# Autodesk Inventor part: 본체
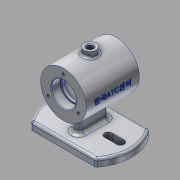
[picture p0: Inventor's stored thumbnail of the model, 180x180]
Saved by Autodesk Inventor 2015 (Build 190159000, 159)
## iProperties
Created: 2017-12
Part Number: 본체
Material: 알루미늄 6061
Document SubType Name: Modeling
Designer: SCD-A03
Density: 2.7 g/cm^3
Appearance: 알루미늄 - 평지
Author: SCD-A03
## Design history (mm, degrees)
sketch "스케치1"
  geometry: C1 r 30 at (0, 0); 1 further point
  constraints: 1 centre point, 1 coincident
  dimensions: "d0" = 60 diameter of C1
extrude "돌출1" new body sketch "스케치1" stored distance "d1" = 70; taper "d2" = 0 deg
node "작업 평면1"
sketch "스케치2"
  geometry: L1 (-42.426, 35)-(42.426, 35); L2 (42.426, -35)-(-42.426, -35); A1 r 55 centre (0, 0) between (-42.426, 35) and (-42.426, -35); A2 r 55 centre (0, 0) between (42.426, -35) and (42.426, 35); 2 further points
  constraints: 4 end point, 4 point on circle, 2 centre point, 1 coincident, 1 horizontal, 1 horizontal alignment, 1 parallel
  dimensions: "d5" = 70 distance between parallel lines of L2 L1; "d6" = 35 distance from line of point (0, 0) L1
extrude "돌출2" join sketch "스케치2" distance "d7" = 10; taper "d8" = 0 deg
sketch "스케치3"
  geometry: L1 (-5, 15.086)-(5, 15.086); L2 (5, 15.086)-(5, -14.914); L3 (5, -14.914)-(-5, -14.914); L4 (-5, -14.914)-(-5, 15.086); A1 r 55 centre (0, 0) between (-42.426, 35) and (-42.426, -35) reference; 3 further points
  constraints: 8 end point, 3 horizontal alignment, 2 midpoint, 2 parallel, 1 horizontal, 1 perpendicular, 4 other
  dimensions: "d18" = 5 distance from line of A1.centre L4; "d19" = 10 distance between parallel lines of L2 L4; "d20" = 30 distance of L1.end L2.end
extrude "돌출3" join sketch "스케치3" stored distance "d12" = 10; taper "d13" = 0 deg
sketch "스케치5"
  geometry: L1 (40, 5)-(24, 5); L2 (24, 5)-(24, -5); L3 (24, -5)-(40, -5); L4 (40, -5)-(40, 5); L5 (0, 0)-(0, -14.914); L6 (-24, 5)-(-24, -5); L7 (-40, 5)-(-24, 5); L8 (-24, -5)-(-40, -5); L9 (-40, -5)-(-40, 5); A1 r 5 centre (0, -14.914) between (-5, -14.914) and (5, -14.914) reference; A2 r 55 centre (0, 0) between (-42.426, 35) and (-42.426, -35) reference; A3 r 55 centre (0, 0) between (42.426, -35) and (42.426, 35) reference; 6 further points
  constraints: 18 end point, 7 symmetric about line, 4 vertical alignment, 3 vertical, 2 coincident, 2 midpoint, 2 parallel, 1 horizontal, 1 horizontal alignment, 1 perpendicular, 8 other
  dimensions: "d21" = 10 distance of L3.end L1.start; "d22" = 24 distance from line of A2.centre L2; "d23" = 16 distance of L2.end L3.end
extrude "돌출4" cut sketch "스케치5" distance "d24" = 10; taper "d25" = 0 deg
sketch "스케치6"
  geometry: C1 r 30 at (0, 0) reference; C2 r 16 at (0, 0)
  constraints: 1 centre point, 1 coincident
  dimensions: "d26" = 32 diameter of C2
extrude "돌출5" cut sketch "스케치6" distance "d27" = 12; taper "d28" = 0 deg
sketch "스케치7"
  geometry: C1 r 16 at (0, 0) reference; C2 r 14 at (0, 0)
  constraints: 1 centre point, 1 coincident
  dimensions: "d29" = 28 diameter of C2
extrude "돌출6" cut sketch "스케치7" distance "d30" = 3; taper "d31" = 0 deg
sketch "스케치8"
  geometry: C1 r 14 at (0, 0) reference; C2 r 25 at (0, 0)
  constraints: 1 centre point, 1 coincident
  dimensions: "d32" = 50 diameter of C2
extrude "돌출7" cut sketch "스케치8" distance "d33" = 40; taper "d34" = 0 deg
node "작업 평면2"
node "작업 평면3"
sketch "스케치9"
  geometry: C1 r 8 at (0, 0); 1 further point
  constraints: 1 centre point, 1 coincident
  dimensions: "d36" = 16 diameter of C1
extrude "돌출8" join sketch "스케치9" stored distance "d37" = 40; taper "d38" = 0 deg
hole "구멍1" diameter "d41" = 8; stored, may be unused: countersink angle "d45" = 90 deg, drill point angle "d47" = 118 deg; dims "d39" = 10, "d40" = 10, "d42" = 6, "d43" = 4, "d44" = 2, "d46" = 20
sketch "스케치10" dims "d48" = 46
  geometry: C1 r 30 at (0, 0) reference; 2 further points
  constraints: 1 coincident, 1 vertical alignment, 2 other
hole "구멍2" sketch "스케치10" at (0, 23) diameter "d49" = 3.242; stored, may be unused: countersink angle "d53" = 90 deg, drill point angle "d55" = 118 deg; dims "d50" = 8, "d51" = 4, "d52" = 2, "d54" = 10
node "작업 평면4"
sketch "스케치11"
  geometry: L1 (-35, 30)-(35, 30) reference; 2 further points
  constraints: 1 other
  dimensions: "d60" = 30 distance from line of point (0, 0) L1
feature "엠보싱1" sketch "스케치11" dims "d18" = 5, "d19" = 10, "d20" = 30, "d61" = 0.5, "d62" = 0
fillet "모깎기1" dims "d63" = 5
fillet "모깎기2" dims "d64" = 3
fillet "모깎기3" dims "d65" = 3
fillet "모깎기4" dims "d66" = 3
chamfer "모따기1" distance "d67" = 1; stored, may be unused: second distance "d68" = 2, angle "d69" = 45 deg
fillet "모깎기5" dims "d70" = 3
fillet "모깎기6" dims "d71" = 0.3
node "솔리드1"
mirror "대칭1"
pattern_circular "원형 패턴1" dims angle "d57" = 360 deg
mirror "대칭2"
other parameters: "d3" = -62, "d35" = 37, "d59" = 35
